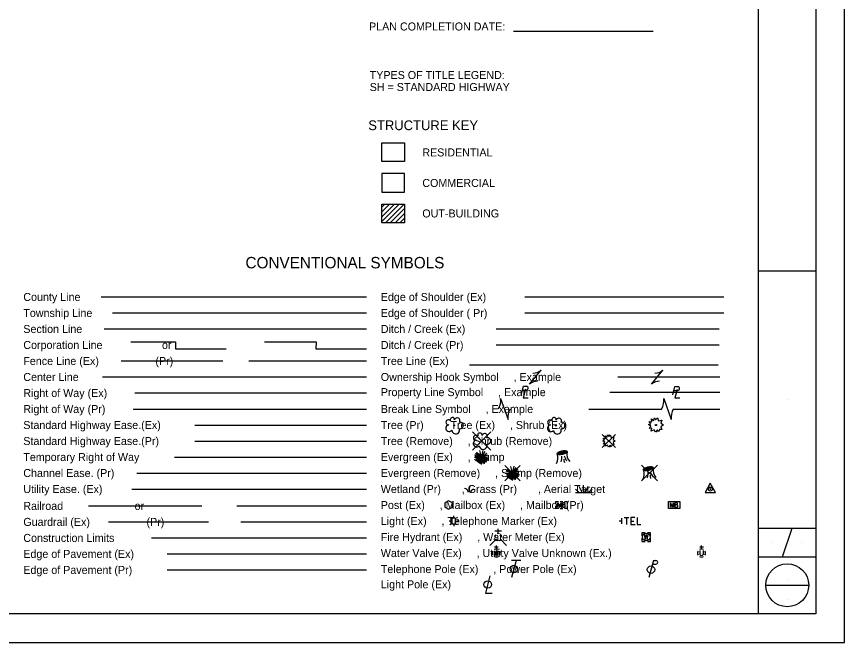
# Model space of a CAD drawing. Extents: x 5.6 to 39.6, y 0.7 to 22.7.
# Drawn here: x 25.08 to 39.55, y 0.71 to 11.66 of the extents above; entities that cross this region are included whole.
import ezdxf

# ---------------------------------------------------------------- set-up
doc = ezdxf.new("R2010")
doc.units = 0
for name, color, linetype in [('SC_Shading1', 7, 'Continuous'), ('SH_Border', 7, 'Continuous'), ('SH_Cut_Line', 7, 'Continuous'), ('SH_Data', 7, 'Continuous'), ('SH_Text', 7, 'Continuous')]:
    doc.layers.add(name, color=color, linetype=linetype)

msp = doc.modelspace()

# ---------------------------------------------------------------- linework, layer by layer
at = {"layer": 'SC_Shading1'}
msp.add_lwpolyline([(31.463, 8.584), (31.86, 8.584), (31.86, 8.91), (31.463, 8.91)], close=True, dxfattribs=at)
at = {"layer": 'SH_Border'}
for p, q in [((38.052, 1.207), (38.052, 22.207)), ((38.052, 7.207), (39.052, 7.207)), ((38.052, 2.707), (39.052, 2.707)), ((38.468, 2.207), (38.635, 2.707)), ((38.052, 2.207), (39.052, 2.207))]:
    msp.add_line(p, q, dxfattribs=at)
msp.add_lwpolyline([(7.552, 22.207), (39.052, 22.207), (39.052, 1.207), (7.552, 1.207)], close=True, dxfattribs=at)
at = {"layer": 'SH_Cut_Line'}
msp.add_lwpolyline([(5.552, 0.707), (39.552, 0.707), (39.552, 22.707), (5.552, 22.707)], close=True, dxfattribs=at)
at = {"layer": 'SH_Data'}
for p, q in [((38.552, 4.957), (38.552, 4.957)), ((38.301, 2.457), (38.301, 2.457)), ((38.801, 2.457), (38.801, 2.457)), ((38.552, 1.792), (38.552, 1.792)), ((38.177, 1.707), (38.927, 1.707)), ((38.552, 1.452), (38.552, 1.452))]:
    msp.add_line(p, q, dxfattribs=at)
msp.add_circle((38.552, 1.707), 0.375, dxfattribs=at)
at = {"layer": 'SH_Text'}
for p, q in [((33.766, 11.402), (36.209, 11.402)), ((31.463, 8.373), (31.464, 8.375)), ((31.463, 8.323), (31.514, 8.375)), ((31.463, 8.238), (31.599, 8.375)), ((31.463, 8.154), (31.684, 8.375)), ((31.463, 8.069), (31.768, 8.375)), ((31.527, 8.049), (31.853, 8.375)), ((31.612, 8.049), (31.86, 8.297)), ((31.697, 8.049), (31.86, 8.212)), ((31.781, 8.049), (31.86, 8.127)), ((31.463, 8.053), (31.467, 8.049)), ((26.557, 6.751), (31.196, 6.751)), ((33.963, 6.751), (37.446, 6.751)), ((26.755, 6.471), (31.196, 6.471)), ((33.963, 6.471), (37.446, 6.471)), ((26.612, 6.191), (31.196, 6.191)), ((33.462, 6.191), (37.362, 6.191)), ((27.076, 5.968), (27.859, 5.968)), ((27.859, 5.968), (27.859, 5.841)), ((27.859, 5.841), (28.74, 5.841)), ((33.462, 5.911), (37.362, 5.911)), ((26.909, 5.631), (28.682, 5.631)), ((29.139, 5.631), (31.196, 5.631)), ((32.994, 5.561), (37.344, 5.561)), ((34.047, 5.228), (34.247, 5.468)), ((36.179, 5.228), (36.379, 5.468)), ((26.578, 5.351), (31.196, 5.351)), ((34.147, 5.348), (34.147, 5.348)), ((35.592, 5.351), (37.375, 5.351)), ((36.279, 5.348), (36.279, 5.348)), ((27.145, 5.071), (31.196, 5.071)), ((33.923, 5.12), (33.988, 5.12)), ((33.963, 5.089), (33.963, 5.089)), ((35.451, 5.086), (37.375, 5.086)), ((36.571, 5.116), (36.636, 5.116)), ((36.611, 5.085), (36.611, 5.085)), ((33.54, 4.975), (33.67, 4.607)), ((36.393, 4.975), (36.523, 4.607)), ((27.118, 4.791), (31.196, 4.791)), ((33.605, 4.791), (33.605, 4.791)), ((35.082, 4.791), (36.358, 4.791)), ((36.458, 4.791), (36.458, 4.791)), ((36.558, 4.791), (37.375, 4.791)), ((28.196, 4.511), (31.196, 4.511)), ((33.048, 4.391), (33.368, 4.071)), ((33.368, 4.391), (33.048, 4.071)), ((35.319, 4.347), (35.55, 4.115)), ((35.55, 4.347), (35.319, 4.115)), ((28.196, 4.231), (31.196, 4.231)), ((33.208, 4.231), (33.208, 4.231)), ((35.434, 4.231), (35.434, 4.231)), ((33.206, 3.951), (33.175, 4.066)), ((33.206, 3.951), (33.237, 4.068)), ((27.841, 3.951), (31.196, 3.951)), ((33.083, 3.951), (33.206, 3.951)), ((33.206, 3.951), (33.096, 3.98)), ((33.206, 3.951), (33.099, 3.912)), ((33.206, 3.951), (33.106, 3.894)), ((33.206, 3.951), (33.108, 4.008)), ((33.206, 3.951), (33.108, 3.876)), ((33.206, 3.951), (33.119, 4.038)), ((33.206, 3.951), (33.132, 3.864)), ((33.206, 3.951), (33.148, 3.851)), ((33.206, 3.951), (33.164, 3.842)), ((33.206, 3.951), (33.174, 3.829)), ((33.206, 3.951), (33.192, 3.836)), ((33.206, 3.951), (33.272, 4.048)), ((33.206, 3.951), (33.297, 4.021)), ((33.206, 3.951), (33.324, 3.991)), ((33.206, 3.951), (33.319, 3.953)), ((33.206, 3.82), (33.206, 3.951)), ((33.206, 3.951), (33.229, 3.835)), ((33.206, 3.951), (33.254, 3.834)), ((33.206, 3.951), (33.269, 3.856)), ((33.206, 3.951), (33.296, 3.863)), ((33.206, 3.951), (33.301, 3.887)), ((33.206, 3.951), (33.318, 3.902)), ((33.206, 3.951), (33.327, 3.927)), ((34.634, 3.951), (34.634, 3.951)), ((33.615, 3.805), (33.882, 3.537)), ((33.882, 3.805), (33.615, 3.537)), ((33.749, 3.671), (33.718, 3.786)), ((33.749, 3.671), (33.78, 3.789)), ((33.749, 3.671), (33.815, 3.768)), ((36.003, 3.81), (36.281, 3.532)), ((36.281, 3.81), (36.003, 3.532)), ((27.179, 3.671), (31.196, 3.671)), ((33.625, 3.671), (33.749, 3.671)), ((33.749, 3.671), (33.638, 3.701)), ((33.749, 3.671), (33.641, 3.632)), ((33.749, 3.671), (33.649, 3.614)), ((33.749, 3.671), (33.651, 3.729)), ((33.749, 3.671), (33.651, 3.596)), ((33.749, 3.671), (33.661, 3.758)), ((33.749, 3.671), (33.675, 3.584)), ((33.749, 3.671), (33.691, 3.571)), ((33.749, 3.671), (33.707, 3.563)), ((33.749, 3.671), (33.717, 3.55)), ((33.749, 3.671), (33.735, 3.556)), ((33.749, 3.671), (33.84, 3.741)), ((33.749, 3.671), (33.867, 3.711)), ((33.749, 3.671), (33.861, 3.673)), ((33.749, 3.54), (33.749, 3.671)), ((33.749, 3.671), (33.772, 3.555)), ((33.749, 3.671), (33.797, 3.554)), ((33.749, 3.671), (33.812, 3.576)), ((33.749, 3.671), (33.838, 3.583)), ((33.749, 3.671), (33.844, 3.607)), ((33.749, 3.671), (33.86, 3.623)), ((33.749, 3.671), (33.869, 3.647)), ((33.749, 3.671), (33.749, 3.671)), ((36.142, 3.671), (36.142, 3.671)), ((36.142, 3.671), (36.142, 3.671)), ((27.095, 3.391), (31.196, 3.391)), ((34.915, 3.33), (34.847, 3.387)), ((34.848, 3.329), (35.14, 3.333)), ((34.964, 3.331), (34.912, 3.437)), ((34.994, 3.331), (34.992, 3.457)), ((35.024, 3.332), (35.073, 3.439)), ((35.073, 3.332), (35.139, 3.391)), ((26.334, 3.096), (28.32, 3.096)), ((28.93, 3.096), (31.196, 3.096)), ((34.58, 3.172), (34.63, 3.172)), ((34.58, 3.05), (34.63, 3.05)), ((34.606, 3.111), (34.606, 3.111)), ((36.573, 3.111), (36.573, 3.111)), ((32.672, 2.88), (32.654, 2.898)), ((32.72, 2.895), (32.72, 2.922)), ((32.787, 2.898), (32.768, 2.88)), ((26.688, 2.816), (28.431, 2.816)), ((29.001, 2.816), (31.196, 2.816)), ((32.668, 2.831), (32.642, 2.831)), ((32.672, 2.783), (32.654, 2.764)), ((32.72, 2.831), (32.72, 2.831)), ((32.72, 2.767), (32.72, 2.741)), ((32.787, 2.764), (32.768, 2.783)), ((32.799, 2.831), (32.772, 2.831)), ((35.661, 2.831), (35.612, 2.831)), ((35.661, 2.781), (35.661, 2.881)), ((33.559, 2.654), (33.439, 2.654)), ((33.499, 2.611), (33.499, 2.697)), ((27.44, 2.536), (31.196, 2.536)), ((33.457, 2.509), (33.353, 2.405)), ((33.5, 2.551), (33.5, 2.551)), ((33.5, 2.551), (33.5, 2.551)), ((33.542, 2.509), (33.646, 2.405)), ((36.087, 2.551), (36.087, 2.551)), ((33.5, 2.373), (33.436, 2.373)), ((33.468, 2.341), (33.468, 2.405)), ((37.085, 2.372), (37.021, 2.372)), ((37.053, 2.34), (37.053, 2.404)), ((27.713, 2.256), (31.196, 2.256)), ((33.468, 2.271), (33.468, 2.271)), ((37.026, 2.313), (37.026, 2.244)), ((37.053, 2.27), (37.053, 2.27)), ((37.08, 2.313), (37.08, 2.244)), ((33.892, 2.141), (33.732, 2.141)), ((33.812, 2.141), (33.732, 1.841)), ((36.213, 2.141), (36.133, 1.841)), ((36.196, 2.077), (36.256, 2.077)), ((36.213, 2.141), (36.256, 2.141)), ((27.713, 1.976), (31.196, 1.976))]:
    msp.add_line(p, q, dxfattribs=at)
for points in [[(31.463, 9.445), (31.86, 9.445), (31.86, 9.119), (31.463, 9.119)], [(31.463, 8.375), (31.86, 8.375), (31.86, 8.049), (31.463, 8.049)], [(37.117, 3.332), (37.297, 3.332), (37.207, 3.493)], [(36.473, 3.172), (36.673, 3.172), (36.673, 3.05), (36.473, 3.05)], [(32.687, 2.781), (32.754, 2.781), (32.754, 2.881), (32.687, 2.881)]]:
    msp.add_lwpolyline(points, close=True, dxfattribs=at)
for points in [[(29.413, 5.968), (30.316, 5.968), (30.31, 5.841), (31.196, 5.841)], [(33.902, 5.041), (33.941, 5.189), (33.993, 5.189)], [(33.976, 5.137), (33.937, 4.989), (34.024, 4.989)], [(36.55, 5.037), (36.589, 5.185), (36.641, 5.185)], [(36.625, 5.133), (36.585, 4.985), (36.672, 4.985)], [(36.251, 4.602), (36.282, 4.638), (36.302, 4.586), (36.357, 4.595), (36.34, 4.544), (36.387, 4.514), (36.344, 4.478), (36.357, 4.432), (36.319, 4.435), (36.303, 4.39), (36.282, 4.424), (36.248, 4.383), (36.226, 4.428), (36.175, 4.406), (36.185, 4.453), (36.144, 4.449), (36.168, 4.489), (36.129, 4.517), (36.166, 4.53), (36.136, 4.57), (36.183, 4.565), (36.181, 4.617), (36.219, 4.588), (36.229, 4.638), (36.251, 4.602)], [(35.431, 4.308), (35.456, 4.339), (35.474, 4.295), (35.521, 4.302), (35.506, 4.259), (35.546, 4.234), (35.51, 4.203), (35.521, 4.164), (35.489, 4.167), (35.475, 4.128), (35.456, 4.157), (35.428, 4.123), (35.409, 4.16), (35.366, 4.142), (35.374, 4.182), (35.34, 4.178), (35.36, 4.212), (35.327, 4.236), (35.359, 4.247), (35.333, 4.282), (35.372, 4.277), (35.371, 4.321), (35.403, 4.297), (35.412, 4.339), (35.431, 4.308)], [(32.567, 3.074), (32.632, 3.036), (32.697, 3.074), (32.697, 3.149), (32.632, 3.186), (32.567, 3.149), (32.567, 3.074)], [(34.506, 3.124), (34.506, 3.172), (34.554, 3.172)], [(34.554, 3.05), (34.506, 3.05), (34.506, 3.099)], [(34.541, 3.071), (34.541, 3.151), (34.57, 3.071), (34.597, 3.151), (34.597, 3.071)], [(34.657, 3.115), (34.66, 3.118), (34.662, 3.12), (34.663, 3.122), (34.664, 3.123), (34.665, 3.125), (34.665, 3.127), (34.667, 3.132), (34.667, 3.133), (34.667, 3.136), (34.666, 3.14), (34.665, 3.143), (34.663, 3.145), (34.66, 3.148), (34.657, 3.149), (34.656, 3.15), (34.653, 3.151), (34.622, 3.151), (34.622, 3.071), (34.657, 3.071), (34.661, 3.074), (34.665, 3.077), (34.668, 3.082), (34.67, 3.087), (34.671, 3.093), (34.671, 3.097), (34.669, 3.101), (34.667, 3.106), (34.664, 3.11), (34.657, 3.115), (34.622, 3.115)], [(34.656, 3.172), (34.706, 3.172), (34.706, 3.124)], [(34.706, 3.099), (34.706, 3.05), (34.656, 3.05)], [(36.508, 3.071), (36.508, 3.151), (36.537, 3.071), (36.564, 3.151), (36.564, 3.071)], [(36.624, 3.115), (36.627, 3.118), (36.629, 3.12), (36.63, 3.122), (36.631, 3.123), (36.632, 3.125), (36.632, 3.127), (36.634, 3.132), (36.634, 3.133), (36.634, 3.136), (36.633, 3.14), (36.632, 3.143), (36.63, 3.145), (36.627, 3.148), (36.624, 3.149), (36.623, 3.15), (36.62, 3.151), (36.589, 3.151), (36.589, 3.071), (36.624, 3.071), (36.628, 3.074), (36.632, 3.077), (36.635, 3.082), (36.637, 3.087), (36.637, 3.093), (36.637, 3.097), (36.636, 3.101), (36.634, 3.106), (36.631, 3.11), (36.624, 3.115), (36.589, 3.115)], [(35.702, 2.893), (35.78, 2.893)], [(35.742, 2.893), (35.742, 2.768)], [(35.887, 2.893), (35.819, 2.893), (35.819, 2.768), (35.892, 2.768)], [(35.819, 2.831), (35.867, 2.831)], [(35.927, 2.893), (35.927, 2.768), (35.994, 2.768)], [(36.067, 2.626), (36.012, 2.626), (36.012, 2.571)], [(36.162, 2.571), (36.162, 2.626), (36.107, 2.626)], [(36.012, 2.531), (36.012, 2.476), (36.067, 2.476)], [(36.053, 2.596), (36.07, 2.506), (36.087, 2.596), (36.103, 2.506), (36.12, 2.596)], [(36.107, 2.476), (36.162, 2.476), (36.162, 2.531)], [(33.436, 2.312), (33.452, 2.226), (33.468, 2.312), (33.484, 2.226), (33.5, 2.312)], [(33.354, 1.87), (33.275, 1.571), (33.393, 1.571)]]:
    msp.add_lwpolyline(points, dxfattribs=at)
for centre, radius in [((32.727, 4.503), 0.0084), ((34.505, 4.5), 0.0072), ((36.255, 4.511), 0.0115), ((33.208, 4.231), 0.0072), ((35.434, 4.231), 0.00979), ((37.207, 3.39), 0.035), ((37.207, 3.39), 0.008), ((36.087, 2.551), 0.0675), ((33.772, 1.991), 0.065), ((36.17, 1.981), 0.065), ((33.315, 1.722), 0.065)]:
    msp.add_circle(centre, radius, dxfattribs=at)
for centre, radius, start, end in [((34.089, 5.683), 0.267, 273.6945, 306.337), ((36.22, 5.683), 0.267, 273.6945, 306.337), ((34.205, 5.013), 0.267, 93.6945, 126.337), ((36.337, 5.013), 0.267, 93.6945, 126.337), ((33.987, 5.155), 0.0345, 270.471, 81.3281), ((36.636, 5.151), 0.0345, 270.471, 81.3281), ((33.208, 4.943), 0.334, 332.9422, 5.5848), ((36.061, 4.943), 0.334, 332.9422, 5.5848), ((34.002, 4.639), 0.334, 152.9422, 185.5848), ((36.855, 4.639), 0.334, 152.9422, 185.5848), ((32.698, 4.604), 0.0395, 354.0047, 205.9741), ((32.782, 4.588), 0.0466, 323.83, 165.0376), ((34.475, 4.601), 0.0395, 354.0047, 205.9741), ((32.642, 4.457), 0.0592, 96.1722, 320.5737), ((32.628, 4.559), 0.0441, 39.0625, 279.5412), ((32.831, 4.504), 0.0574, 259.1453, 101.4596), ((34.419, 4.453), 0.0592, 96.1722, 320.5737), ((34.405, 4.555), 0.0441, 39.0625, 279.5412), ((34.559, 4.584), 0.0466, 323.83, 165.0376), ((34.608, 4.501), 0.0574, 259.1453, 101.4596), ((32.756, 4.425), 0.0685, 184.9476, 19.4572), ((33.179, 4.332), 0.0395, 354.0047, 205.9741), ((33.263, 4.316), 0.0466, 323.83, 165.0376), ((34.533, 4.421), 0.0685, 184.9476, 19.4572), ((33.122, 4.185), 0.0592, 96.1722, 320.5737), ((33.109, 4.287), 0.0441, 39.0625, 279.5412), ((33.312, 4.232), 0.0574, 259.1453, 101.4596), ((33.236, 4.153), 0.0685, 184.9476, 19.4572), ((34.342, 3.934), 0.2, 331.5338, 20.9269), ((34.358, 3.952), 0.253, 340.7938, 3.5481), ((34.829, 3.911), 0.182, 178.7926, 197.1224), ((34.959, 4.054), 0.316, 194.9653, 212.1216), ((34.914, 4.008), 0.215, 171.4106, 219.9194), ((35.85, 3.654), 0.2, 331.5338, 20.9269), ((35.866, 3.672), 0.253, 340.7938, 3.5481), ((36.337, 3.631), 0.182, 178.7926, 197.1224), ((36.467, 3.774), 0.316, 194.9653, 212.1216), ((36.422, 3.728), 0.215, 171.4106, 219.9194), ((33.5, 2.551), 0.06, 68.1395, 112.038), ((33.5, 2.551), 0.06, 140.021, 184.0629), ((33.5, 2.551), 0.06, 211.8788, 255.8479), ((33.5, 2.551), 0.06, 283.8239, 329.9097), ((33.5, 2.551), 0.06, 356.0165, 39.9889), ((33.468, 2.271), 0.07, 60.0184, 120.0157), ((37.053, 2.27), 0.07, 60.0184, 120.0157), ((33.468, 2.271), 0.07, 150.0184, 209.9816), ((33.468, 2.271), 0.07, 239.9843, 299.9816), ((33.468, 2.271), 0.07, 330.0184, 29.9816), ((37.053, 2.27), 0.07, 150.0184, 209.9816), ((37.053, 2.27), 0.07, 239.9843, 299.9816), ((37.053, 2.257), 0.03, 205.1924, 334.8076), ((37.053, 2.27), 0.07, 330.0184, 29.9816), ((36.256, 2.109), 0.0319, 268.8767, 91.1233)]:
    msp.add_arc(centre, radius, start, end, dxfattribs=at)
for centre, major_axis in [((34.615, 4.027), (0.0868, 0.0187)), ((34.615, 4.027), (0.0651, 0.0141)), ((34.615, 4.027), (0.0488, 0.0105)), ((34.615, 4.027), (0.0275, 0.0059)), ((34.615, 4.027), (0.0154, 0.0033)), ((36.123, 3.747), (0.0868, 0.0187)), ((36.123, 3.747), (0.0651, 0.0141)), ((36.123, 3.747), (0.0488, 0.0105)), ((36.123, 3.747), (0.0275, 0.0059)), ((36.123, 3.747), (0.0154, 0.0033))]:
    msp.add_ellipse(centre, major_axis=major_axis, ratio=0.36865, dxfattribs=at)
for points in [[(32.909, 3.407), (32.951, 3.389), (32.969, 3.336)], [(32.997, 3.34), (32.997, 3.387), (33.003, 3.431), (33.012, 3.452)], [(33.025, 3.333), (33.036, 3.371), (33.066, 3.395)]]:
    msp.add_spline(points, degree=3, dxfattribs=at)

# ---------------------------------------------------------------- texts
for s, height, p in [('PLAN COMPLETION DATE:', 0.14, (31.24, 11.412)), ('TYPES OF TITLE LEGEND:', 0.14, (31.252, 10.563)), ('SH = STANDARD HIGHWAY ', 0.14, (31.252, 10.353)), ('STRUCTURE KEY', 0.17, (31.227, 9.669)), ('RESIDENTIAL', 0.14, (32.172, 9.209)), ('COMMERCIAL', 0.14, (32.172, 8.675)), ('OUT-BUILDING', 0.14, (32.172, 8.142)), ('CONVENTIONAL SYMBOLS', 0.2, (29.08, 7.251)), ('County Line', 0.14, (25.196, 6.681)), ('Edge of Shoulder (Ex)', 0.14, (31.446, 6.681)), ('Township Line', 0.14, (25.196, 6.401)), ('Edge of Shoulder ( Pr)', 0.14, (31.446, 6.401)), ('Section Line', 0.14, (25.196, 6.121)), ('Ditch / Creek (Ex)', 0.14, (31.446, 6.121)), ('Corporation Line                    or', 0.14, (25.196, 5.841)), ('Ditch / Creek (Pr)', 0.14, (31.446, 5.841)), ('Fence Line (Ex)                   (Pr)', 0.14, (25.196, 5.561)), ('Tree Line (Ex)', 0.14, (31.446, 5.561)), ('Center Line', 0.14, (25.196, 5.281)), ('Ownership Hook Symbol     , Example', 0.14, (31.446, 5.281)), ('Right of Way (Ex)', 0.14, (25.196, 5.001)), ('Property Line Symbol     , Example', 0.14, (31.446, 5.016)), ('Right of Way (Pr)', 0.14, (25.196, 4.721)), ('Break Line Symbol     , Example', 0.14, (31.446, 4.721)), ('Standard Highway Ease.(Ex)', 0.14, (25.196, 4.441)), ('Tree (Pr)       , Tree (Ex)     , Shrub (Ex)', 0.14, (31.446, 4.441)), ('Standard Highway Ease.(Pr)', 0.14, (25.196, 4.161)), ('Tree (Remove)     , Shrub (Remove)', 0.14, (31.446, 4.161)), ('Temporary Right of Way', 0.14, (25.196, 3.881)), ('Evergreen (Ex)     , Stump ', 0.14, (31.446, 3.881)), ('Channel Ease. (Pr)', 0.14, (25.196, 3.601)), ('Evergreen (Remove)     , Stump (Remove)', 0.14, (31.446, 3.601)), ('Utility Ease. (Ex)', 0.14, (25.196, 3.321)), ('Wetland (Pr)       , Grass (Pr)       , Aerial Target    ', 0.14, (31.446, 3.321)), ('Post (Ex)     , Mailbox (Ex)     , Mailbox (Pr)', 0.14, (31.446, 3.041)), ('Railroad                        or', 0.14, (25.196, 3.026)), ('Light (Ex)     , Telephone Marker (Ex)     ', 0.14, (31.446, 2.761)), ('Guardrail (Ex)                   (Pr)', 0.14, (25.196, 2.746)), ('Construction Limits', 0.14, (25.196, 2.466)), ('Fire Hydrant (Ex)     , Water Meter (Ex)', 0.14, (31.446, 2.481)), ('Edge of Pavement (Ex)', 0.14, (25.196, 2.186)), ('Water Valve (Ex)     , Utility Valve Unknown (Ex.)', 0.14, (31.446, 2.201)), ('Edge of Pavement (Pr)', 0.14, (25.196, 1.906)), ('Telephone Pole (Ex)     , Power Pole (Ex)', 0.14, (31.446, 1.921)), ('Light Pole (Ex)     ', 0.14, (31.446, 1.654))]:
    msp.add_text(s, height=height, dxfattribs=at).set_placement(p)

doc.saveas('drawing.dxf')
